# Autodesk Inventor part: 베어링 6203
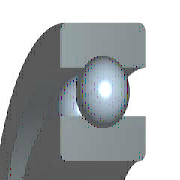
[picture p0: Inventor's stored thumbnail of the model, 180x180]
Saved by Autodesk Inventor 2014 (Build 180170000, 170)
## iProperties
IsCustomPart: 0
Company: 한국ATC센터
Created: 2015-11
Part Number: 베어링 6203
Material: 강철, 연강
Description: 깊은 그루브 볼 베어링
Document SubType Name: Modeling
Standard: KS B 2023
Designer: mdu
Standards Organization: KS
Language: ko-KR
Size Designation: 6203 - 17 x 40 x 12
Categories: <MemberInstance><Categories><Category DisplayName="샤프트 부품" InternalName="7f7aeb1f-a693-4053-b835-cee3144e0d98" Mnemonic="SHFT"><Category DisplayName="베어링" Inter
Density: 7.86 g/cm^3
Mass: 64.9809 g
Surface Area: 64.3582 cm^2
Volume: 8.26729 cm^3
Appearance: 노란색
Author: mdu
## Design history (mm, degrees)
sketch "스케치" dims "d0" = 5.98 (= -0.26 x WD + 0.26 x BD)
  geometry: L1 (3.01, 14.25)-(8.99, 14.25); L2 (6, 14.25)-(6, 11.26); L3 (6, 14.25)-(6, 17.24); L4 (3.778, 12.249)-(0, 12.249); L5 (0, 8.5)-(12, 8.5); L6 (3.778, 16.251)-(0, 16.251); L7 (0, 20)-(12, 20); L8 (12, 8.5)-(12, 12.249); L9 (8.222, 12.249)-(12, 12.249); L10 (8.222, 16.251)-(12, 16.251); L11 (12, 20)-(12, 16.251); L12 (-1.4, 0)-(8.4, 0) reference; L13 (0, -0.3)-(0, 5.3) reference
  constraints: 22 end point, 4 point on line, 2 collinear, 2 perpendicular, 2 symmetric about line, 1 midpoint, 1 parallel, 14 other
  dimensions: "d9" = 17 diameter of L5 L12 (= WD); "d11" = 40 diameter of L7 L12 (= BD); "d12" = 12 distance between parallel lines of L8 L13 (= KB); "d13" = 24.498 diameter of L9 L12 (= 0.326 x BD + 0.674 x WD)
revolve "본체" stored, may be unused: angle "d6" = 90 deg
revolve "볼" stored, may be unused: angle "d7" = 90 deg
pattern_circular "IDS_ARRAYBALL[SIMPL:T]" dims angle "d3" = 360 deg
body "Solid1"
fillet "모깎기1" dims "d1" = 0.6 (= KRS)
other parameters: "WD" = 17 [user parameter; used in 5 equation terms], "BD" = 40 [user parameter; used in 5 equation terms], "KB" = 12 [user parameter; used in 1 equation term], "KRS" = 0.6 [user parameter; used in 1 equation term], "d4" = 0, "d5" = 0, "d8" = 0, "d14" = 0, "d15" = 0, "BBA" = 0 [user parameter], "BC0" = 4750000 [user parameter], "BC" = 9560000 [user parameter], "WR" = 8.5 (= 0.5 x WD) [user parameter]
